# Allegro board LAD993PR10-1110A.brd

Outline 310.04 x 134.8 mm; copper layers: TOP, GND1, IN1, VCC, IN2, IN3, GND2, IN4, GND3, BOTTOM. Coordinates in mm from the lower left corner of the outline.

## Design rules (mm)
constraint set DEFAULT: min track width 0.114
net group CLK_S15(12)/20(15): nets CLK_PCIE_SSD CLK_PCIE_SSD#
net group DDI1_DDPB_CTRLDAT: nets DDI1_DDPB_CTRLCLK DDI1_DDPB_CTRLDAT
net group DIFFPAIR0: nets DMIC_CLK_CAM DMIC_DATA_CAM
net group DIFFPAIR1: nets CLK_SMB DAT_SMB
net group DIFFPAIR2: nets TMDS_L_TX2N TMDS_L_TX2P
net group DIFFPAIR3: nets TMDS_L_TX1N TMDS_L_TX1P
net group DIFFPAIR4: nets TMDS_L_TX0N TMDS_L_TX0P
net group DIFFPAIR5: nets TMDS_L_TXCN TMDS_L_TXCP
net group DP1: nets N123984002 N123984213
net group DP2: nets N123984081 N123985122
net group DP3: nets N57527 V3N
net group DP4: nets N122477585 V2N
net group DP5: nets N122476680 V1N
net group DP6: nets ISUMN_SA ISUMP_SA
net group DP12: nets GNDS_SENSE_VGA VDDS_SENSE_VGA
net group DP13: nets VCCSA_SENSE VSSSA_SENSE
net group DP_I2CB_SCL: nets I2CB_SCL SYS_PEX_RST_MON#
net group DP_N35924928: nets N35924928 N35928308
net group DP_STRAP: nets STRAP1 STRAP2
net group HDMI: nets TMDS_T_TX1N TMDS_T_TX1P
net group RTC: nets PCH_RTCX1 PCH_RTCX2
net group S-18(12)/18(12): nets XTAL_OUT XTALIN
net group SATA: nets SATA_PTX_DRX_N1B_RC SATA_PTX_DRX_P1B_RC
net group USB2.0: nets USBP2_R_D+ USBP2_R_D-
net group VSS_SENSE: nets VCCGT_SENSE VSSGT_SENSE
net group W-16: nets +FBA_VREFC0 +FBC_VREFC1
net group W-60: nets +EDPVDD +INV_PWR_SRC
net group 50H_W4.5(3.7)-T14B: nets CLK_PCI_LPC_MEC CLK_PCI_LPDEBUG CLKOUT_LPC0 CLKOUT_LPC1
net group 85H-CLK_4.3/3.6/3.6/4.3-T14B: nets CLK_PCIE_LAN CLK_PCIE_LAN# CLK_PCIE_WLAN CLK_PCIE_WLAN# CLK_PEG_N16P CLK_PEG_N16P# CPU_24MHZ_N CPU_24MHZ_P PCH_CPU_BCLK_N PCH_CPU_BCLK_P PCH_CPU_PCIBCLK_N PCH_CPU_PCIBCLK_P
net group 85H-PCIE_4.3/3.6/3.6/4.3-T14B: nets SATA_PRX_SSDTX_N0A SATA_PRX_SSDTX_P0A SATA_PTX_SSDRX_N0A SATA_PTX_SSDRX_N0A_C SATA_PTX_SSDRX_P0A SATA_PTX_SSDRX_P0A_C
net group DDRAC_S12/25: nets DDR_CKE0_DIMMA DDR_CKE1_DIMMA DDR_CS0_DIMMA# DDR_CS1_DIMMA# M_ODT0 M_ODT1
net group DDRAD0_S8/25: nets DDR_A_D0 DDR_A_D1 DDR_A_D2 DDR_A_D3 DDR_A_D4 DDR_A_D5 DDR_A_D6 DDR_A_D7
net group DDRAD1_S8/25: nets DDR_A_D8 DDR_A_D9 DDR_A_D10 DDR_A_D11 DDR_A_D12 DDR_A_D13 DDR_A_D14 DDR_A_D15
net group DDRAD2_S8/25: nets DDR_A_D16 DDR_A_D17 DDR_A_D18 DDR_A_D19 DDR_A_D20 DDR_A_D21 DDR_A_D22 DDR_A_D23
net group DDRAD3_S8/25: nets DDR_A_D24 DDR_A_D25 DDR_A_D26 DDR_A_D27 DDR_A_D28 DDR_A_D29 DDR_A_D30 DDR_A_D31
net group DDRAD4_S8/25: nets DDR_A_D32 DDR_A_D33 DDR_A_D34 DDR_A_D35 DDR_A_D36 DDR_A_D37 DDR_A_D38 DDR_A_D39
net group DDRAD5_S8/25: nets DDR_A_D40 DDR_A_D41 DDR_A_D42 DDR_A_D43 DDR_A_D44 DDR_A_D45 DDR_A_D46 DDR_A_D47
net group DDRAD6_S8/25: nets DDR_A_D48 DDR_A_D49 DDR_A_D50 DDR_A_D51 DDR_A_D52 DDR_A_D53 DDR_A_D54 DDR_A_D55
net group DDRAD7_S8/25: nets DDR_A_D56 DDR_A_D57 DDR_A_D58 DDR_A_D59 DDR_A_D60 DDR_A_D61 DDR_A_D62 DDR_A_D63
net group DDRAMA_S12/25: nets DDR_A_ACT# DDR_A_ALERT# DDR_A_BG0 DDR_A_BG1 DDR_A_BS0 DDR_A_BS1 DDR_A_CAS# DDR_A_MA0 DDR_A_MA1 DDR_A_MA2 DDR_A_MA3 DDR_A_MA4 DDR_A_MA5 DDR_A_MA6 DDR_A_MA7 DDR_A_MA8 DDR_A_MA9 DDR_A_MA10 DDR_A_MA11 DDR_A_MA12 DDR_A_MA13 DDR_A_PAR DDR_A_RAS# DDR_A_WE#
net group DDRBC_S12/25: nets DDR_CKE2_DIMMB DDR_CKE3_DIMMB DDR_CS2_DIMMB# DDR_CS3_DIMMB# M_ODT2 M_ODT3
net group DDRBD0_S8/25: nets DDR_B_D0 DDR_B_D1 DDR_B_D2 DDR_B_D3 DDR_B_D4 DDR_B_D5 DDR_B_D6 DDR_B_D7
net group DDRBD1_S8/25: nets DDR_B_D8 DDR_B_D9 DDR_B_D10 DDR_B_D11 DDR_B_D12 DDR_B_D13 DDR_B_D14 DDR_B_D15
net group DDRBD2_S8/25: nets DDR_B_D16 DDR_B_D17 DDR_B_D18 DDR_B_D19 DDR_B_D20 DDR_B_D21 DDR_B_D22 DDR_B_D23
net group DDRBD3_S8/25: nets DDR_B_D24 DDR_B_D25 DDR_B_D26 DDR_B_D27 DDR_B_D28 DDR_B_D29 DDR_B_D30 DDR_B_D31
net group DDRBD4_S8/25: nets DDR_B_D32 DDR_B_D33 DDR_B_D34 DDR_B_D35 DDR_B_D36 DDR_B_D37 DDR_B_D38 DDR_B_D39
net group DDRBD5_S8/25: nets DDR_B_D40 DDR_B_D41 DDR_B_D42 DDR_B_D43 DDR_B_D44 DDR_B_D45 DDR_B_D46 DDR_B_D47
net group DDRBD6_S8/25: nets DDR_B_D48 DDR_B_D49 DDR_B_D50 DDR_B_D51 DDR_B_D52 DDR_B_D53 DDR_B_D54 DDR_B_D55
net group DDRBD7_S8/25: nets DDR_B_D56 DDR_B_D57 DDR_B_D58 DDR_B_D59 DDR_B_D60 DDR_B_D61 DDR_B_D62 DDR_B_D63
net group DDRBMA_S12/25: nets DDR_B_ACT# DDR_B_ALERT# DDR_B_BG0 DDR_B_BG1 DDR_B_BS0 DDR_B_BS1 DDR_B_CAS# DDR_B_MA0 DDR_B_MA1 DDR_B_MA2 DDR_B_MA3 DDR_B_MA4 DDR_B_MA5 DDR_B_MA6 DDR_B_MA7 DDR_B_MA8 DDR_B_MA9 DDR_B_MA10 DDR_B_MA11 DDR_B_MA12 DDR_B_MA13 DDR_B_PAR DDR_B_RAS# DDR_B_WE#
net group DDRCLK_S16/25: nets M_CLK_DDR0 M_CLK_DDR1 M_CLK_DDR2 M_CLK_DDR3 M_CLK_DDR#0 M_CLK_DDR#1 M_CLK_DDR#2 M_CLK_DDR#3
net group DDRDQS_S25/25: nets DDR_A_DQS0 DDR_A_DQS1 DDR_A_DQS2 DDR_A_DQS3 DDR_A_DQS4 DDR_A_DQS5 DDR_A_DQS6 DDR_A_DQS7 DDR_A_DQS#0 DDR_A_DQS#1 DDR_A_DQS#2 DDR_A_DQS#3 DDR_A_DQS#4 DDR_A_DQS#5 DDR_A_DQS#6 DDR_A_DQS#7 DDR_B_DQS0 DDR_B_DQS1 DDR_B_DQS2 DDR_B_DQS3 DDR_B_DQS4 DDR_B_DQS5 DDR_B_DQS6 DDR_B_DQS7 DDR_B_DQS#0 DDR_B_DQS#1 DDR_B_DQS#2 DDR_B_DQS#3 DDR_B_DQS#4 DDR_B_DQS#5 DDR_B_DQS#6 DDR_B_DQS#7
net group DMI_S12/15: nets DMI_CRX_PTX_N0 DMI_CRX_PTX_N1 DMI_CRX_PTX_N2 DMI_CRX_PTX_N3 DMI_CRX_PTX_P0 DMI_CRX_PTX_P1 DMI_CRX_PTX_P2 DMI_CRX_PTX_P3 DMI_CTX_PRX_N0 DMI_CTX_PRX_N1 DMI_CTX_PRX_N2 DMI_CTX_PRX_N3 DMI_CTX_PRX_P0 DMI_CTX_PRX_P1 DMI_CTX_PRX_P2 DMI_CTX_PRX_P3
net group DP_FBC_ABI#_L: nets FBC_ABI#_L
net group EDP_S12/15: nets EDP_AUXN EDP_AUXN_C EDP_AUXN_R EDP_AUXP EDP_AUXP_C EDP_AUXP_R EDP_TXN0 EDP_TXN0_C EDP_TXN0_R EDP_TXN1 EDP_TXN1_C EDP_TXN1_R EDP_TXN2 EDP_TXN2_C EDP_TXN2_R EDP_TXN3 EDP_TXN3_C EDP_TXN3_R EDP_TXP0 EDP_TXP0_C EDP_TXP0_R EDP_TXP1 EDP_TXP1_C EDP_TXP1_R EDP_TXP2 EDP_TXP2_C EDP_TXP2_R EDP_TXP3 EDP_TXP3_C EDP_TXP3_R
net group FBCLK_S(20)12/(20)12: nets FBA_CLK0 FBA_CLK0# FBA_CLK1 FBA_CLK1# FBC_CLK0 FBC_CLK0# FBC_CLK1 FBC_CLK1#
net group FBCMD_S20(16)/20(16): nets FBC_ABI#_H FBC_CAS#_L FBC_MA0_MA10_L FBC_MA1_MA9_L FBC_MA2_BA0_L FBC_MA4_BA2_H FBC_MA6_MA11_H FBC_MA7_MA8_H FBC_MA12_RFU_L FBC_RST#_L FBC_WE#_H
net group FBWCK_S16/16: nets FBA_WCK0 FBA_WCK0_N FBA_WCK1 FBA_WCK1_N FBA_WCK2 FBA_WCK2_N FBA_WCK3 FBA_WCK3_N FBC_WCK0 FBC_WCK0_N FBC_WCK1 FBC_WCK1_N FBC_WCK2 FBC_WCK2_N FBC_WCK3 FBC_WCK3_N
net group HDMI_S16(12)/16(12): nets IFPC_CLK_CN IFPC_CLK_CP IFPC_CLK_N IFPC_CLK_P IFPC_TX0_CN IFPC_TX0_CP IFPC_TX0_N IFPC_TX0_P IFPC_TX1_CN IFPC_TX1_CP IFPC_TX1_N IFPC_TX1_P IFPC_TX2_CN IFPC_TX2_CP IFPC_TX2_N IFPC_TX2_P TMDS_T_TX0N TMDS_T_TX0P TMDS_T_TX2N TMDS_T_TX2P TMDS_T_TXCN TMDS_T_TXCP
net group LAN_S30/30: nets MDI0+ MDI0- MDI1+ MDI1- MDI2+ MDI2- MDI3+ MDI3- MDO0+ MDO0- MDO1+ MDO1- MDO2+ MDO2- MDO3+ MDO3-
net group PCIE_S12/15: nets PCIE_PRX_LANTX_N3_C PCIE_PRX_LANTX_N5 PCIE_PRX_LANTX_P3_C PCIE_PRX_LANTX_P5 PCIE_PRX_SSDTX_N10 PCIE_PRX_SSDTX_N11 PCIE_PRX_SSDTX_N12 PCIE_PRX_SSDTX_P10 PCIE_PRX_SSDTX_P11 PCIE_PRX_SSDTX_P12 PCIE_PRX_WLANTX_N6 PCIE_PRX_WLANTX_P6 PCIE_PTX_LANRX_N5 PCIE_PTX_LANRX_N5_C PCIE_PTX_LANRX_P5 PCIE_PTX_LANRX_P5_C PCIE_PTX_SSDRX_N10 PCIE_PTX_SSDRX_N10_C PCIE_PTX_SSDRX_N11 PCIE_PTX_SSDRX_N11_C PCIE_PTX_SSDRX_N12 PCIE_PTX_SSDRX_N12_C PCIE_PTX_SSDRX_P10 PCIE_PTX_SSDRX_P10_C PCIE_PTX_SSDRX_P11 PCIE_PTX_SSDRX_P11_C PCIE_PTX_SSDRX_P12 PCIE_PTX_SSDRX_P12_C PCIE_PTX_WLANRX_N6 PCIE_PTX_WLANRX_P6 PCIE_PTX_WLANRX_RE_N6 PCIE_PTX_WLANRX_RE_P6
net group PEG_S12/15: nets PEG_GTX_C_HRX_N0 PEG_GTX_C_HRX_N1 PEG_GTX_C_HRX_N2 PEG_GTX_C_HRX_N3 PEG_GTX_C_HRX_N4 PEG_GTX_C_HRX_N5 PEG_GTX_C_HRX_N6 PEG_GTX_C_HRX_N7 PEG_GTX_C_HRX_N8 PEG_GTX_C_HRX_N9 PEG_GTX_C_HRX_N10 PEG_GTX_C_HRX_N11 PEG_GTX_C_HRX_N12 PEG_GTX_C_HRX_N13 PEG_GTX_C_HRX_N14 PEG_GTX_C_HRX_N15 PEG_GTX_C_HRX_P0 PEG_GTX_C_HRX_P1 PEG_GTX_C_HRX_P2 PEG_GTX_C_HRX_P3 PEG_GTX_C_HRX_P4 PEG_GTX_C_HRX_P5 PEG_GTX_C_HRX_P6 PEG_GTX_C_HRX_P7 PEG_GTX_C_HRX_P8 PEG_GTX_C_HRX_P9 PEG_GTX_C_HRX_P10 PEG_GTX_C_HRX_P11 PEG_GTX_C_HRX_P12 PEG_GTX_C_HRX_P13 PEG_GTX_C_HRX_P14 PEG_GTX_C_HRX_P15 PEG_GTX_HRX_N0 PEG_GTX_HRX_N1 PEG_GTX_HRX_N2 PEG_GTX_HRX_N3 PEG_GTX_HRX_N4 PEG_GTX_HRX_N5 PEG_GTX_HRX_N6 PEG_GTX_HRX_N7 PEG_GTX_HRX_N8 PEG_GTX_HRX_N9 PEG_GTX_HRX_N10 PEG_GTX_HRX_N11 PEG_GTX_HRX_N12 PEG_GTX_HRX_N13 PEG_GTX_HRX_N14 PEG_GTX_HRX_N15 PEG_GTX_HRX_P0 PEG_GTX_HRX_P1 PEG_GTX_HRX_P2 PEG_GTX_HRX_P3 PEG_GTX_HRX_P4 PEG_GTX_HRX_P5 PEG_GTX_HRX_P6 PEG_GTX_HRX_P7 PEG_GTX_HRX_P8 PEG_GTX_HRX_P9 PEG_GTX_HRX_P10 PEG_GTX_HRX_P11 PEG_GTX_HRX_P12 PEG_GTX_HRX_P13 PEG_GTX_HRX_P14 PEG_GTX_HRX_P15 PEG_HTX_C_GRX_N0 PEG_HTX_C_GRX_N1 PEG_HTX_C_GRX_N2 PEG_HTX_C_GRX_N3 PEG_HTX_C_GRX_N4 PEG_HTX_C_GRX_N5 PEG_HTX_C_GRX_N6 PEG_HTX_C_GRX_N7 PEG_HTX_C_GRX_N8 PEG_HTX_C_GRX_N9 PEG_HTX_C_GRX_N10 PEG_HTX_C_GRX_N11 PEG_HTX_C_GRX_N12 PEG_HTX_C_GRX_N13 PEG_HTX_C_GRX_N14 PEG_HTX_C_GRX_N15 PEG_HTX_C_GRX_P0 PEG_HTX_C_GRX_P1 PEG_HTX_C_GRX_P2 PEG_HTX_C_GRX_P3 PEG_HTX_C_GRX_P4 PEG_HTX_C_GRX_P5 PEG_HTX_C_GRX_P6 PEG_HTX_C_GRX_P7 PEG_HTX_C_GRX_P8 PEG_HTX_C_GRX_P9 PEG_HTX_C_GRX_P10 PEG_HTX_C_GRX_P11 PEG_HTX_C_GRX_P12 PEG_HTX_C_GRX_P13 PEG_HTX_C_GRX_P14 PEG_HTX_C_GRX_P15 PEG_HTX_GRX_N0 PEG_HTX_GRX_N1 PEG_HTX_GRX_N2 PEG_HTX_GRX_N3 PEG_HTX_GRX_N4 PEG_HTX_GRX_N5 PEG_HTX_GRX_N6 PEG_HTX_GRX_N7 PEG_HTX_GRX_N8 PEG_HTX_GRX_N9 PEG_HTX_GRX_N10 PEG_HTX_GRX_N11 PEG_HTX_GRX_N12 PEG_HTX_GRX_N13 PEG_HTX_GRX_N14 PEG_HTX_GRX_N15 PEG_HTX_GRX_P0 PEG_HTX_GRX_P1 PEG_HTX_GRX_P2 PEG_HTX_GRX_P3 PEG_HTX_GRX_P4 PEG_HTX_GRX_P5 PEG_HTX_GRX_P6 PEG_HTX_GRX_P7 PEG_HTX_GRX_P8 PEG_HTX_GRX_P9 PEG_HTX_GRX_P10 PEG_HTX_GRX_P11 PEG_HTX_GRX_P12 PEG_HTX_GRX_P13 PEG_HTX_GRX_P14 PEG_HTX_GRX_P15
net group POWER-20: nets 1.2V_DDR_OT 1V8_GFX_RUN 1VS_GFX_PG 3VS 3VS_TP 5VS +0.6VS +0.6VSP +0.95VSP +1.0VSP +1.2V_DDR +1.2V_DDRP +1.2V_PWROK +1.2V_VCCPLL_OC +1.8V_AVDD +1.8V_DVDD +1.8V_GFX_RUN +1.8V_PLLVDD +1.8VS +1.8VSP +1.35VS_VGA +1.35VS_VGAP +1.35VS_VGAP_B+ +1V_MPHY +1V_MPHY_MPHYPLL +1V_PCH +1V_PCH_AZPLL +1V_PCH_CLK5 +1V_PCH_PRIM +1V_PCH_USBPLL +1V_VCCDSW +1VALWP +1VS_GFX +3.3VDX_SSD +3V_DVDD +3V_PCH_AZIO +3V_PCH_DSW +3V_PCH_SPI +3V_ROM +3VALWP +3VLP +3VS_CAM +3VS_TP +3VS_WLAN +5V_AVDD +5V_CHGUSB_1 +5V_CHGUSB_2 +5V_PVDD +5VALWP +5VS +5VS_HDD +5VS_KBL +5VS_TS +19VB_1VALWP +19VB_+0.95VSP +19VB_+1.0VSP +19VB_+1.8VSP +CHGRTC +DC_IN +DCPRTC +GPCPLL_AVDD +GPU_CORE_VDDS +IFP_PLLVDD +LAN_VDD +NVVDDS_B+ +PEX_PLL_HVDD +SP_PLLVDD +V_DAC +VCCIO +VCCIO_PG +VCCST +VCCSTG +VDISPLAY_VCC +VGA_B+ -DC_IN B++ B+_CAM BATT++ BST_3V BST_5V CHG_B+ DH1_NVVDD DH1_NVVDDS DH2_NVVDD DL1_NVVDD DL1_NVVDDS DL2_NVVDD EC_AGND FB_3V FB_5V GVDD LDO_1VALWP LDO_+0.95VSP LDO_+1.0VSP LDO_+1.8VSP LG_3V LG_5V LX1_NVVDD LX1_NVVDDS LX2_NVVDD LX_1VALWP LX_3V LX_5V LX_+0.95VSP LX_+1.0VSP LX_+1.8VSP LX_CHG N120976432 N121795600 N122017994 N123983992 N123984041 N123984461 N128731318 N128835022 N128884118 N128885130 N129089927 N129090627 N131680753 N131681151 N131748830 PQ703_S SNUB_+0.95VSP SNUB_+1.0VSP SNUB_+1.8VSP SW_+1.35VS_VGAP UG_3V UG_5V VBATT VCCGT_B+ VCCST VCCSTG VCORE_B+ VIN
net group S-5(4)/5(4): nets DDC_CLK_HDMI DDC_DAT_HDMI IFPC_I2C_CLK IFPC_I2C_DAT
net group S_10/10: nets CODEC_SDOUT_R N131741387 REMOTE1+ REMOTE1- REMOTE2+ REMOTE2- VCCSENSE_VGA VR_SVID_ALERT# VR_SVID_ALERT#_C VR_SVID_ALERT#_R VR_SVID_CLK VR_SVID_CLK_C VR_SVID_DATA VR_SVID_DATA_C VSSSENSE_VGA
net group S_12/12: nets EC_SPI_CS# EC_SPI_CS#_R EC_SPI_SI EC_SPI_SI_R EC_SPI_SO EC_SPI_SO_R PCH_SPI_CS# PCH_SPI_HOLD# PCH_SPI_HOLD#_R PCH_SPI_SI PCH_SPI_SI_R PCH_SPI_SO PCH_SPI_SO_R PCH_SPI_WP# PCH_SPI_WP#_R PCIE_RCOMPN PCIE_RCOMPP
net group S_15/15: nets CODEC_BITCLK_R H_DRAMRST# LPC_LAD0 LPC_LAD1 LPC_LAD2 LPC_LAD3 LPC_LFRAME# MEC_XTAL1 MEC_XTAL1_R MEC_XTAL2 PCH_DPWROK PCH_PLTRST# PCH_PWROK PCH_RSMRST# PCH_RSMRST#_R PCH_RTCRST# PCH_SRTCRST# PEG_RCOMP SYS_PWROK SYS_RESET# XTAL24_IN XTAL24_OUT XTALOUT XTALSSIN XTLI XTLO
net group S_20/20: nets EC_SPI_CLK EC_SPI_CLK_R H_CPUPWRGD H_VCCST_PWRGD HDA_BITCLK HDA_BITCLK_AUDIO PCH_SPI_CLK PCH_SPI_CLK_R PECI_EC PECI_EC_R PLTRST_CPU# VCCST_PWRGD_CPU
net group S_25/25: nets EDP_COMP
net group SATA_PRX_DTX_P1B_RC: nets SATA_PRX_DTX_N1B_RC
net group SATA_S12/15: nets SATA_PRX_DTX_N1B SATA_PRX_DTX_P1B SATA_PRX_DTX_P1B_RC SATA_PTX_DRX_N1B SATA_PTX_DRX_P1B
net group SM: nets PCH_SMBCLK SMBCLK SML0_SMBCLK SML1_SMBCLK SUSCLK SUSCLK_R
net group USB2.0_S12/15: nets USB20_N1 USB20_N2 USB20_N3 USB20_N4 USB20_N4_R USB20_N7 USB20_N9 USB20_N9_R USB20_N12 USB20_N12_R USB20_P1 USB20_P2 USB20_P3 USB20_P4 USB20_P4_R USB20_P7 USB20_P9 USB20_P9_R USB20_P12 USB20_P12_R USBP1_R_D+ USBP1_R_D- USBP2_D+ USBP2_D-
net group USB3.0_S12/15: nets USB3RN1 USB3RN1_D- USB3RN2 USB3RN2_D- USB3RN3 USB3RP1 USB3RP1_D+ USB3RP2 USB3RP2_D+ USB3RP3 USB3T_N1 USB3T_N2 USB3T_P1 USB3T_P2 USB3TN1 USB3TN1_D- USB3TN2 USB3TN2_D- USB3TN3 USB3TP1 USB3TP1_D+ USB3TP2 USB3TP2_D+ USB3TP3
net group W-10: nets FBVDDQ_SENSE VCC_SENSE VCCIO_SENSE VSS_SENSE VSSIO_SENSE
net group W-20: nets +RTCBATT +RTCVCC +RTCVCC_VBAT +V_DDR_REFA +V_DDR_REFA_R +V_DDR_REFB +V_DDR_REFB_R
net group W-40: nets +LAN_IO AUD_PORTA_L_R_B AUD_PORTA_R_R_B AUD_SPK_L+ AUD_SPK_L+_C AUD_SPK_L- AUD_SPK_L-_C AUD_SPK_R+ AUD_SPK_R+_C AUD_SPK_R- AUD_SPK_R-_C RING2 RING2_R SLEEVE SLEEVE_R
net group W-50OHM: nets CLKREQ_PCIE#0 CLKRUN# H_CATERR# H_PROCHOT# H_PROCHOT#_R H_PROCHOT_EC H_THERMTRIP# H_THERMTRIP#_R HDA_CODEC_SDIN0 HDA_SDIN0 HDA_SDIN0_AUDIO HDA_SDOUT HDA_SDOUT_AUDIO HDA_SYNC HDA_SYNC_AUDIO LAN_CLKREQ# PECI SRCCLKREQ1# SRCCLKREQ4# SRCCLKREQ5# SRCCLKREQ7# SRCCLKREQ8# SRCCLKREQ9# SRCCLKREQ10# SRCCLKREQ11# SRCCLKREQ13# SRCCLKREQ14# SRCCLKREQ15# SSD_CLK_REQ# USB2_COMP VGA_CLK_REQ# WLAN_CLK_REQ#
nets with their own width: min track width 0.254; nets N18094850 N19473597
nets with their own width: min track width 0.381; nets N19473413
nets with their own width: min track width 0.508; nets 5VS_FAN2 +2.5V_MEM +2.5VSP_ON GND N128884110 N131311358
nets with their own width: min track width 0.635; nets +5VALW

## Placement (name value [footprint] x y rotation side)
CA1  4.7U_0603_6.3V6K  [C_0603]  288.17 27.49 0 top
CA2  0.1U_0402_10V6K  [C_0402]  288.41 28.57 0 top
CA3  0.1U_0402_10V6K  [C_0402]  285.63 28.57 0 top
CA4  1U_0402_6.3V6K  [C_0402]  290.2 39.03 90 top
CA7  1U_0402_6.3V6K  [C_0402]  289.77 33.07 180 top
CA8  4.7U_0603_6.3V6K  [C_0603]  275.66 20.82 180 top
CA9  0.1U_0402_10V6K  [C_0402]  275.42 21.96 180 top
CA10  0.68U_0603_16V6K  [C_0603]  285.19 37.96 0 top
CA11  10U_0603_6.3V6M~D  [C_0603]  278.33 30.98 90 top
CA12  0.1U_0402_10V6K  [C_0402]  279.41 30.9 90 top
CA13  10U_0603_6.3V6M~D  [C_0603]  280.49 30.98 90 top
CA14  0.1U_0402_10V6K  [C_0402]  281.57 30.9 90 top
CA15  1U_0402_6.3V6K  [C_0402]  286.55 27.68 180 top
CA16  2.2U_0402_6.3V6M  [C_0402]  287.74 23.51 180 top
CA17  0.1U_0402_10V6K  [C_0402]  284.62 20.13 270 top
CA18  4.7U_0603_6.3V6K  [C_0603]  287.66 18.98 90 top
CA19  4.7U_0603_6.3V6K  [C_0603]  287.98 22.47 180 top
CA20  1U_0402_6.3V6K  [C_0402]  285.63 28.45 270 bottom
CA21  1U_0402_6.3V6K  [C_0402]  283.73 20.13 270 top
CA22  10U_0603_6.3V6M  [C_0603]  284.49 29.64 180 bottom
CA23  10U_0603_6.3V6M  [C_0603]  281.63 21.58 180 bottom
CA24  0.1U_0402_10V6K  [C_0402]  278.47 20.06 180 top
CA25  4.7U_0603_6.3V6K  [C_0603]  275.66 19.55 180 top
CA26  0.1U_0402_10V6K  [C_0402]  275.42 27.55 180 top
CA27  4.7U_0603_6.3V6K  [C_0603]  275.92 24.88 180 top
CA28  0.1U_0402_10V6K  [C_0402]  275.42 22.85 180 top
CA29  0.1U_0402_10V6K  [C_0402]  279.83 17.45 90 top
CA30  22P_0402_50V8J  [C_0402]  272.22 25.45 0 top
CA31  .1U_0402_16V7K  [C_0402]  273.64 25.9 180 bottom
CA32  .1U_0402_16V7K  [C_0402]  275.41 23.92 90 bottom
CA33  33P_0402_50V8J  [C_0402]  272.68 24.04 90 bottom
CA34  0.01U_0201_16V7  [C_0201]  270.46 22.56 90 top
CA35  0.01U_0201_16V7  [C_0201]  273.25 22.68 90 top
CA36  1000P_0402_50V7K  [C_0402]  278.06 15.66 180 top
CA37  1000P_0402_50V7K  [C_0402]  275.37 15.66 0 top
CA38  1000P_0402_50V7K  [C_0402]  273.24 15.66 180 top
CA39  1000P_0402_50V7K  [C_0402]  270.55 15.66 0 top
CA40  100P_0402_50V8J  [C_0402]  292.57 18.91 180 top
CA41  100P_0402_50V8J  [C_0402]  296.48 16.88 0 top
CA42  100P_0402_50V8J  [C_0402]  296.99 12.06 0 bottom
CA43  100P_0402_50V8J  [C_0402]  293.25 18.23 270 bottom
CA44  680P_0402_50V7K  [C_0402]  259.39 10.71 180 bottom
CA45  680P_0402_50V7K  [C_0402]  261.81 10.71 0 bottom
CA46  330P_0402_50V7K  [C_0402]  257.92 14.67 0 bottom
CA47  330P_0402_50V7K  [C_0402]  268.26 15.2 0 bottom
CA48  0.22U_0603_50V7K  [C_0603]  258.99 16.98 270 bottom
CA49  0.22U_0603_50V7K  [C_0603]  261.25 14.62 0 bottom
CA50  0.22U_0603_50V7K  [C_0603]  264.42 14.62 0 bottom
CA51  0.22U_0603_50V7K  [C_0603]  268.08 16.14 90 bottom
CA52  1000P_0402_50V7K  [C_0402]  258.79 18.79 180 bottom
CA53  10U_0603_25V6M  [C_0603]  258.85 19.83 180 bottom
CA54  1000P_0402_50V7K  [C_0402]  268.27 20.58 0 top
CA55  0.1U_0402_25V6  [C_0402]  271.79 18.84 90 top
CA56  10U_0603_25V6M  [C_0603]  270.65 18.85 90 top
CA57  0.1U_0402_25V6  [C_0402]  258.79 17.9 180 bottom
CA60  680P_0402_50V7K  [C_0402]  296.98 9.36 225 bottom
CA61  680P_0402_50V7K  [C_0402]  294.14 18.23 270 bottom
CA62  10P_0402_25V8J  [C_0402]  275.42 26.66 180 top
CA63  10U_0603_6.3V6M  [C_0603]  284.49 29.64 180 top
CA64  10U_0603_6.3V6M~D  [C_0603]  295.41 15.55 270 top
CA65  10U_0603_6.3V6M~D  [C_0603]  294.14 15.55 270 top
CA66  1U_0603_25V6  [C_0603]  258.9 27.04 0 bottom
CA67  0.1U_0402_25V6  [C_0402]  262.9 30.65 90 bottom
CC4  12P_0402_50V8J  [C_0402]  169.47 16.47 0 top
CC5  12P_0402_50V8J  [C_0402]  184.28 24.28 0 top
CC27  1U_0402_6.3V6K  [C_0402]  154.52 18.82 270 bottom
CC298  0.1U_0402_16V7K  [C_0402]  131.66 75.43 180 top
CD1  1U_0402_6.3V6K  [C_0402]  96.61 42.79 180 top
CD2  1U_0402_6.3V6K  [C_0402]  79.85 43.03 0 top
CD3  1U_0402_6.3V6K  [C_0402]  138.65 41.12 0 top
CD4  1U_0402_6.3V6K  [C_0402]  138.65 40.24 0 top
CD5  10U_0603_6.3V6M  [C_0603]  112.62 44.43 0 top
CD6  10U_0603_6.3V6M  [C_0603]  102.05 44.44 0 top
CD7  10U_0603_6.3V6M  [C_0603]  131.9 43.81 180 top
CD8  10U_0603_6.3V6M  [C_0603]  89.76 44.05 180 top
CD9  10U_0603_6.3V6M  [C_0603]  138.64 39.09 180 top
CD10  10U_0603_6.3V6M  [C_0603]  137.23 41.6 270 top
CD11  330U_X_2VM_R6M  [C_X]  91.53 15.48 180 bottom
CD12  1U_0402_6.3V6K  [C_0402]  138.11 31.23 0 top
CD13  10U_0603_6.3V6M  [C_0603]  136.6 29.96 180 top
CD14  10U_0603_6.3V6M  [C_0603]  136.6 31.23 180 top
CD15  10U_0603_6.3V6M  [C_0603]  138.12 29.96 0 top
CD16  0.1U_0402_10V6K  [C_0402]  135.8 43.08 90 top
CD17  2.2U_0402_6.3V6M  [C_0402]  134.91 43.08 90 top
CD19  1U_0402_6.3V6K  [C_0402]  94.42 19.55 0 top
CD20  1U_0402_6.3V6K  [C_0402]  83.88 19.68 0 top
CD21  1U_0402_6.3V6K  [C_0402]  102.71 19.52 0 top
CD22  1U_0402_6.3V6K  [C_0402]  109.46 19.52 180 top
CD23  10U_0603_6.3V6M  [C_0603]  121.39 28.41 180 top
CD24  10U_0603_6.3V6M  [C_0603]  132.69 28.54 180 top
CD25  10U_0603_6.3V6M  [C_0603]  116.82 19.78 0 top
CD26  10U_0603_6.3V6M  [C_0603]  104.34 28.57 0 top
CD27  10U_0603_6.3V6M  [C_0603]  141.61 26.47 270 top
CD28  10U_0603_6.3V6M  [C_0603]  140.34 26.47 270 top
CD29  0.1U_0402_10V6K  [C_0402]  113.32 19.58 90 top
CD30  1U_0402_6.3V6K  [C_0402]  138.86 27.69 90 top
CD31  1U_0402_6.3V6K  [C_0402]  139.75 27.69 90 top
CD32  1U_0402_6.3V6K  [C_0402]  136.32 22.13 180 top
CD33  330U_2.5V_M  [C_APXK2R5ARA331MF451]  145.93 31.74 180 bottom
CD34  0.1U_0402_10V6K  [C_0402]  136.28 27.6 90 top
CD35  2.2U_0402_6.3V6M  [C_0402]  135.39 27.6 90 top
CD36  4.7U_0603_6.3V6K  [C_0603]  218.32 35.04 0 bottom
CD37  0.22U_0402_10V6K  [C_0402]  205.11 35.91 270 bottom
CD38  0.1U_0402_10V6K  [C_0402]  217.43 19.55 0 bottom
CD39  0.01U_0402_16V7K  [C_0402]  218.47 31.99 0 bottom
CD40  47P_0402_50V8J  [C_0402]  217.43 18.66 0 bottom
CD41  15P_0402_50V8J  [C_0402]  218.47 33.01 0 bottom
CD42  0.22U_0402_10V6K  [C_0402]  204.23 35.91 270 bottom
CD43  0.22U_0402_10V6K  [C_0402]  203.21 35.91 270 bottom
CD44  0.22U_0402_10V6K  [C_0402]  202.32 35.91 270 bottom
CD45  0.22U_0402_10V6K  [C_0402]  201.3 35.91 270 bottom
CD46  0.22U_0402_10V6K  [C_0402]  200.42 35.91 270 bottom
CD51  0.22U_0402_10V6K  [C_0402]  198.51 35.91 270 bottom
CD53  0.22U_0402_10V6K  [C_0402]  199.4 35.91 270 bottom
CD69  .1U_0402_16V7K  [C_0402]  96 16.63 90 bottom
CD70  10U_0603_6.3V6M  [C_0603]  123.17 43.28 0 top
CD71  10U_0603_6.3V6M  [C_0603]  116.94 32.49 0 top
CD72  10U_0603_6.3V6M  [C_0603]  100.34 31.68 90 top
CD73  10U_0603_6.3V6M  [C_0603]  96.75 43.92 180 top
CD74  1U_0402_6.3V6K  [C_0402]  84.06 32.36 180 top
CD75  1U_0402_6.3V6K  [C_0402]  94.7 32.5 180 top
CD76  1U_0402_6.3V6K  [C_0402]  127.62 32.23 180 top
CD77  1U_0402_6.3V6K  [C_0402]  102.04 43.3 0 top
CD78  1U_0402_6.3V6K  [C_0402]  106.34 32.41 90 top
CD79  1U_0402_6.3V6K  [C_0402]  112.61 43.28 0 top
CD80  1U_0402_6.3V6K  [C_0402]  98.39 19.52 0 top
CD81  1U_0402_6.3V6K  [C_0402]  127.34 19.52 0 top
CD82  1U_0402_6.3V6K  [C_0402]  104.61 19.52 0 top
CD83  1U_0402_6.3V6K  [C_0402]  100.42 19.52 0 top
CD84  10U_0603_6.3V6M  [C_0603]  113.13 28.54 0 top
CD85  10U_0603_6.3V6M  [C_0603]  98.15 28.41 180 top
CD86  10U_0603_6.3V6M  [C_0603]  87.83 30.47 180 top
CD87  10U_0603_6.3V6M  [C_0603]  73.35 19.8 180 top
CD88  10U_0603_6.3V6M  [C_0603]  137.84 21.55 0 top
CD89  10U_0603_6.3V6M  [C_0603]  137.84 20.28 0 top
CD90  10U_0603_6.3V6M  [C_0603]  136.81 20.28 180 top
CD91  1U_0402_6.3V6K  [C_0402]  258.76 21.78 180 bottom
CD92  1U_0402_6.3V6K  [C_0402]  258.84 22.72 90 bottom
CD93  1U_0402_6.3V6K  [C_0402]  260.94 22.98 180 bottom
CD94  1U_0402_6.3V6K  [C_0402]  263.66 23.03 90 bottom
CD95  1U_0402_6.3V6K  [C_0402]  264.55 23.03 90 bottom
CD96  0.1U_0402_10V6K  [C_0402]  113.92 32.13 90 top
CE1  0.1U_0402_10V7K~D  [C_0402]  213.24 34.33 90 top
CE2  0.1U_0402_10V6K  [C_0402]  134.82 16.11 0 top
CE4  1U_0402_6.3V6K  [C_0402]  121.67 15.76 90 top
CE5  1U_0402_6.3V6K  [C_0402]  126.32 15.84 180 top
CE6  10U_0603_6.3V6M~D  [C_0603]  122.62 15.97 0 top
CE8  0.047U_0402_16V4Z  [C_0402]  240.85 27.7 0 top
CE9  22P_0402_50V8J  [C_0402]  147.15 14.37 180 bottom
CE10  22P_0402_50V8J  [C_0402]  147.15 15.33 180 bottom
CE12  1U_0402_6.3V6K  [C_0402]  221.93 29.89 0 bottom
CE62  0.1U_0402_10V6K  [C_0402]  236.31 24.88 180 bottom
CE63  1000P_0402_50V7K  [C_0402]  231.78 35.37 270 top
CE64  1000P_0402_50V7K  [C_0402]  239.74 18.02 180 top
CE65  0.1U_0402_10V6K  [C_0402]  217.26 22.6 180 top
CE66  0.1U_0402_10V6K  [C_0402]  226.96 29.66 270 bottom
CE67  0.1U_0402_10V6K  [C_0402]  224.14 15.1 0 bottom
CE68  0.1U_0402_10V6K  [C_0402]  236.18 18.28 180 bottom
CE69  0.1U_0402_10V6K  [C_0402]  220.99 29 90 bottom
CE71  0.1U_0402_10V6K  [C_0402]  227.25 15.56 0 bottom
CE72  0.047U_0402_10V7K~D  [C_0402]  227.25 16.53 0 bottom
CE73  0.1U_0402_10V6K  [C_0402]  224.29 34.46 90 bottom
CE74  0.1U_0402_10V6K  [C_0402]  217.26 21.71 180 top
CE76  100P_0402_50V8J  [C_0402]  235.98 34.46 90 top
CE77  0.1U_0402_10V6K  [C_0402]  236.05 29.58 180 bottom
CE78  4.7P_0402_50V8C  [C_0402]  228.1 13.02 270 top
CE79  0.1U_0402_10V6K  [C_0402]  220.86 23.03 90 bottom
CE80  22P_0402_50V8J  [C_0402]  150.73 15.08 270 bottom
CE81  0.1U_0402_10V6K  [C_0402]  228.86 26.58 90 bottom
CE82  1000P_0402_50V7K  [C_0402]  232.99 21.48 180 bottom
CE84  100P_0402_50V8J  [C_0402]  221.62 32.07 270 bottom
CE85  0.1U_0402_10V6K  [C_0402]  236.31 27.55 180 bottom
CE86  47P_0402_50V8J  [C_0402]  236.31 25.77 180 bottom
CE87  2200P_0402_25V7K  [C_0402]  231.66 27.5 270 bottom
CE89  10U_0603_6.3V6M  [C_0603]  238.71 19.17 0 top
CE91  0.1U_0402_10V6K  [C_0402]  223.58 23.03 180 bottom
CE98  0.1U_0402_10V6K  [C_0402]  228.8 29.66 270 bottom
CE99  0.01U_0402_16V7K  [C_0402]  52.97 31.03 90 top
CE100  0.01U_0402_16V7K  [C_0402]  242.28 38.09 180 top
CE101  10P_0402_25V8J  [C_0402]  221.7 35.42 180 top
CE102  10P_0402_25V8J  [C_0402]  222.69 35.42 0 top
CE103  1U_0603_25V6  [C_0603]  213.38 22.8 90 top
CE104  0.1U_0402_10V6K  [C_0402]  227.34 32.12 0 bottom
CH5  0.22U_0201_6.3V6M  [C_0201]  134.63 92.75 0 bottom
CH6  0.22U_0201_6.3V6M  [C_0201]  134.63 93.39 0 bottom
CH7  0.22U_0201_6.3V6M  [C_0201]  136.15 91.73 0 bottom
CH8  0.22U_0201_6.3V6M  [C_0201]  136.15 92.37 0 bottom
CH9  0.22U_0201_6.3V6M  [C_0201]  134.63 90.72 0 bottom
CH10  0.22U_0201_6.3V6M  [C_0201]  134.63 91.35 0 bottom
CH11  0.22U_0201_6.3V6M  [C_0201]  136.15 90.34 0 bottom
CH12  0.22U_0201_6.3V6M  [C_0201]  136.15 89.7 0 bottom
CH13  0.22U_0201_6.3V6M  [C_0201]  134.63 88.69 0 bottom
CH14  0.22U_0201_6.3V6M  [C_0201]  134.63 89.32 0 bottom
CH15  0.22U_0201_6.3V6M  [C_0201]  136.15 88.31 0 bottom
CH16  0.22U_0201_6.3V6M  [C_0201]  136.15 87.67 0 bottom
CH17  0.22U_0201_6.3V6M  [C_0201]  134.63 86.65 0 bottom
CH18  0.22U_0201_6.3V6M  [C_0201]  134.63 87.29 0 bottom
CH19  0.22U_0201_6.3V6M  [C_0201]  136.15 85.64 0 bottom
CH20  0.22U_0201_6.3V6M  [C_0201]  136.15 86.27 0 bottom
CH21  0.22U_0201_6.3V6M  [C_0201]  134.63 85.26 0 bottom
CH22  0.22U_0201_6.3V6M  [C_0201]  134.63 84.62 0 bottom
CH23  0.22U_0201_6.3V6M  [C_0201]  136.15 83.61 0 bottom
CH24  0.22U_0201_6.3V6M  [C_0201]  136.15 84.24 0 bottom
CH25  0.22U_0201_6.3V6M  [C_0201]  134.63 83.23 0 bottom
CH26  0.22U_0201_6.3V6M  [C_0201]  134.63 82.59 0 bottom
CH27  0.22U_0201_6.3V6M  [C_0201]  136.15 81.57 0 bottom
CH28  0.22U_0201_6.3V6M  [C_0201]  136.15 82.21 0 bottom
CH29  0.22U_0201_6.3V6M  [C_0201]  134.63 81.19 0 bottom
CH30  0.22U_0201_6.3V6M  [C_0201]  134.63 80.56 0 bottom
CH31  0.22U_0201_6.3V6M  [C_0201]  136.15 79.54 0 bottom
CH32  0.22U_0201_6.3V6M  [C_0201]  136.15 80.18 0 bottom
CH33  0.22U_0201_6.3V6M  [C_0201]  134.63 79.16 0 bottom
CH34  0.22U_0201_6.3V6M  [C_0201]  134.63 78.53 0 bottom
CH35  0.22U_0201_6.3V6M  [C_0201]  136.15 77.51 0 bottom
CH36  0.22U_0201_6.3V6M  [C_0201]  136.15 78.15 0 bottom
CH45  8.2P_0402_50V8D  [C_0402]  175.48 18.07 0 bottom
CH46  8.2P_0402_50V8D  [C_0402]  174.62 18.07 180 bottom
CH47  15P_0402_50V8J  [C_0402]  182.89 45 90 bottom
CH48  18P_0402_50V8J  [C_0402]  182.89 44.14 270 bottom
CH50  10P_0402_25V8J  [C_0402]  179.38 18.79 0 bottom
CH51  10P_0402_25V8J  [C_0402]  175.29 25.43 0 top
CH52  1U_0402_6.3V6K  [C_0402]  174.63 22.93 270 top
CH53  1U_0402_6.3V6K  [C_0402]  174.51 19.75 270 top
CH70  0.1U_0402_10V6K  [C_0402]  165.74 23.05 270 top
CH80  1U_0402_6.3V6K  [C_0402]  168.6 25.76 90 top
CH82  1U_0402_6.3V6K  [C_0402]  171.33 34.92 90 top
CH100  0.022U_0402_16V7K  [C_0402]  110.37 20.51 270 top
CH101  0.022U_0402_16V7K  [C_0402]  68.16 44.8 0 top
CH102  10U_0603_6.3V6M  [C_0603]  123.23 85.02 90 top
CH103  10U_0603_6.3V6M  [C_0603]  123.2 87.68 90 top
CH104  10U_0603_6.3V6M  [C_0603]  123.19 91.57 270 top
CH106  1U_0402_6.3V6K  [C_0402]  125.04 96.44 0 top
CH110  1U_0402_6.3V6K  [C_0402]  123.2 93.59 270 top
CH111  10U_0603_6.3V6M  [C_0603]  120.25 96.14 270 top
CH112  10U_0603_6.3V6M  [C_0603]  121.74 85.23 180 top
CH113  10U_0603_6.3V6M  [C_0603]  123.64 97.65 0 top
CH114  10U_0603_6.3V6M  [C_0603]  121.79 86.58 180 top
CH115  10U_0603_6.3V6M  [C_0603]  120.48 98.99 90 top
CH116  10U_0603_6.3V6M  [C_0603]  123.64 98.87 0 top
CH117  10U_0603_6.3V6M  [C_0603]  124.15 100.09 0 top
CH118  10U_0603_6.3V6M  [C_0603]  101.24 80.62 90 top
CH119  10U_0603_6.3V6M  [C_0603]  106.02 80.43 90 top
CH120  10U_0603_6.3V6M  [C_0603]  102.88 76.63 270 top
CH121  10U_0603_6.3V6M  [C_0603]  99.25 78.51 0 top
CH122  10U_0603_6.3V6M  [C_0603]  107.72 79.99 90 top
CH123  10U_0603_6.3V6M  [C_0603]  113.87 76.57 180 top
CH124  10U_0603_6.3V6M  [C_0603]  99.59 80.62 90 top
CH125  10U_0603_6.3V6M  [C_0603]  111.35 79.32 90 top
CH126  10U_0603_6.3V6M  [C_0603]  117.99 76.63 270 top
CH127  10U_0603_6.3V6M  [C_0603]  121.74 81.4 180 top
CH128  10U_0603_6.3V6M  [C_0603]  123.18 76.4 0 top
CH129  22U_0603_6.3V6M  [C_0603]  124.66 60.7 0 top
CH130  22U_0603_6.3V6M  [C_0603]  124.66 59.3 0 top
CH131  22U_0603_6.3V6M  [C_0603]  124.66 57.9 0 top
CH132  22U_0603_6.3V6M  [C_0603]  124.66 56.51 0 top
CH133  1U_0402_6.3V6K  [C_0402]  122.68 100.04 90 top
CH134  1U_0402_6.3V6K  [C_0402]  121.12 101.32 180 top
CH135  1U_0402_6.3V6K  [C_0402]  120.69 98.08 180 top
CH136  47U_0603_6.3V6M  [C_0603]  121.65 92.24 180 top
CH173  0.1U_0402_10V6K  [C_0402]  167.71 25.76 90 top
CH176  1U_0402_6.3V6K  [C_0402]  165.11 24.68 90 top
CH177  22U_0603_6.3V6M  [C_0603]  183.65 38.41 90 bottom
CH178  22U_0603_6.3V6M  [C_0603]  182.38 38.41 90 bottom
CH179  1U_0402_6.3V6K  [C_0402]  181.49 38.39 90 top
CH180  1U_0402_6.3V6K  [C_0402]  155.66 42.79 180 top
CH181  22U_0603_6.3V6M  [C_0603]  157.81 45.84 180 top
CH182  22U_0603_6.3V6M  [C_0603]  155.39 45.84 180 top
CH183  1U_0402_6.3V6K  [C_0402]  165.98 36.23 180 top
CH184  10U_0402_6.3V6M  [C_0402]  167.27 37.12 90 top
CH185  10U_0402_6.3V6M  [C_0402]  166.38 37.12 90 top
CH186  0.1U_0402_10V6K  [C_0402]  170.85 24.32 90 top
CH187  1U_0402_6.3V6K  [C_0402]  178.71 21.57 0 top
CH188  1U_0402_6.3V6K  [C_0402]  173.42 32.46 0 top
CH189  0.1U_0402_10V7K  [C_0402]  175.73 26.53 180 top
CH190  0.1U_0402_10V7K  [C_0402]  159 32.36 180 top
CH191  0.1U_0402_10V7K  [C_0402]  158.84 28.82 180 top
CH192  0.1U_0402_10V7K  [C_0402]  155.9 22.99 270 top
CH197  0.1U_0402_10V7K  [C_0402]  81.4 83.1 180 bottom
CH200  0.1U_0402_10V6K  [C_0402]  171.97 25.24 90 top
CH201  22U_0603_6.3V6M  [C_0603]  177.81 28.69 90 top
CH202  22U_0603_6.3V6M  [C_0603]  176.6 29.07 180 top
CH203  0.1U_0402_10V6K  [C_0402]  170.95 28.13 270 top
CH204  1U_0402_6.3V6K  [C_0402]  123.19 94.65 180 top
CI9  0.1U_0402_10V6K  [C_0402]  286.45 51.55 0 bottom
CI10  0.1U_0402_10V6K  [C_0402]  286.45 50.66 0 bottom
CI11  47U_0805_6.3V6M  [C_0805]  293.72 45.84 180 bottom
CI12  10U_0603_6.3V6M  [C_0603]  293.57 47.36 180 bottom
CI13  0.1U_0402_10V6K  [C_0402]  293.46 48.5 180 bottom
CI16  0.1U_0402_10V6K  [C_0402]  285.43 32.38 0 bottom
CI17  47U_0805_6.3V6M  [C_0805]  292.83 28.44 180 top
CI18  10U_0603_6.3V6M  [C_0603]  292.81 26.91 180 top
CI19  0.1U_0402_10V6K  [C_0402]  292.82 25.77 180 top
CI20  0.1U_0402_10V6K  [C_0402]  285.43 31.49 0 bottom
CI23  0.1U_0402_10V6K  [C_0402]  282.84 38.27 90 top
CI24  1U_0402_6.3V6K  [C_0402]  290.41 40.38 180 bottom
CL15  0.1U_0402_10V6K  [C_0402]  289.62 46.09 0 bottom
CL19  0.1U_0402_10V6K  [C_0402]  282.48 48.89 0 bottom
CL20  0.1U_0402_10V6K  [C_0402]  285.58 46.79 180 top
CL21  0.1U_0402_10V6K  [C_0402]  283.98 42.71 90 top
CL22  0.1U_0402_10V6K  [C_0402]  287.42 46.79 180 top
CL24  0.1U_0402_10V6K  [C_0402]  282.46 40.71 270 bottom
CL30  0.1U_0402_10V6K  [C_0402]  288.55 39.79 90 bottom
CL31  0.1U_0402_10V6K  [C_0402]  287.66 39.79 90 bottom
CL32  0.1U_0402_10V6K  [C_0402]  283.98 45.53 270 top
CL33  10P_1206_2KV8J  [C_1206]  289.97 97.33 125.8 bottom
CL34  0.1U_0402_10V6K  [C_0402]  285.25 40.66 270 bottom
CL35  1U_0402_6.3V6K  [C_0402]  284.36 40.66 270 bottom
CL36  10P_0402_25V8J  [C_0402]  281.82 45 90 bottom
CL37  10P_0402_25V8J  [C_0402]  281.82 44.14 270 bottom
CL39  1U_0402_6.3V6K  [C_0402]  280.68 52.29 90 bottom
CL41  0.01U_0402_16V7K  [C_0402]  294.52 84.01 270 top
CL42  0.1U_0402_10V7K  [C_0402]  283.35 40.71 270 bottom
CL43  4.7U_0402_6.3V6M  [C_0402]  289.62 46.98 0 bottom
CL44  4.7U_0402_6.3V6M  [C_0402]  283.35 47.28 90 top
CL47  0.1U_0402_10V6K  [C_0402]  290.54 44.69 180 bottom
CL48  0.1U_0402_10V6K  [C_0402]  290.54 43.81 180 bottom
CLRP1  SHORT PADS  [SHORTPADS]  176.29 14.21 180 bottom
CM3  0.01U_0402_16V7K  [C_0402]  264.35 37.28 0 bottom
CM4  0.1U_0402_10V6K  [C_0402]  264.35 34.58 0 bottom
CM10  0.1U_0402_10V6K  [C_0402]  271.08 36.12 180 bottom
CM11  0.1U_0402_10V6K  [C_0402]  271.08 37.19 180 bottom
CM12  0.01U_0402_16V7K  [C_0402]  271.08 34.92 180 bottom
CM24  1U_0402_6.3V6K  [C_0402]  263.79 41.14 90 top
CM141  0.1U_0402_10V6K  [C_0402]  264.35 35.93 0 bottom
CM228  4.7U_0603_6.3V6K  [C_0603]  265.06 39.04 90 bottom
CM229  0.01U_0402_16V7K  [C_0402]  269.12 41.27 90 top
CM823  0.01U_0402_16V7K  [C_0402]  272.68 31.36 0 top
CM837  0.1U_0402_10V6K  [C_0402]  272.68 32.25 0 top
CM838  0.1U_0402_10V6K  [C_0402]  267.73 29.96 270 top
CM839  0.1U_0402_10V6K  [C_0402]  268.61 29.96 270 top
CM840  0.1U_0402_10V6K  [C_0402]  272.55 40 0 top
CM841  0.01U_0402_16V7K  [C_0402]  272.55 39.11 0 top
CM842  0.1U_0402_10V6K  [C_0402]  263.92 29.96 270 top
CM843  0.1U_0402_10V6K  [C_0402]  272.81 34.1 270 top
CN1  22U_0603_6.3V6M  [C_0603]  186.46 28.84 90 top
CN2  .1U_0402_16V7K  [C_0402]  184.52 28.9 90 top
CN6  22U_0603_6.3V6M  [C_0603]  199.78 29.01 90 top
CN7  .1U_0402_16V7K  [C_0402]  201.43 29 90 top
CN8  .1U_0402_16V7K  [C_0402]  185.4 28.9 90 top
CN9  1000P_0402_50V7K  [C_0402]  202.32 29 90 top
CN20  0.1U_0402_10V7K  [C_0402]  192.29 35.88 270 bottom
CN21  0.1U_0402_10V7K  [C_0402]  191.4 35.88 270 bottom
CS12  1000P_0402_50V7K  [C_0402]  194.95 18.58 90 bottom
CS13  0.1U_0402_10V6K  [C_0402]  195.84 18.58 90 bottom
CS14  1U_0402_6.3V6K  [C_0402]  196.73 18.58 90 bottom
CS15  10U_0603_6.3V6M  [C_0603]  197.86 18.32 90 bottom
CS25  0.01U_0402_16V7K  [C_0402]  192.16 17.47 270 top
CS26  0.01U_0402_16V7K  [C_0402]  193.05 17.47 270 top
CS27  0.01U_0402_16V7K  [C_0402]  191.14 17.47 270 top
CS28  0.01U_0402_16V7K  [C_0402]  190.26 17.47 270 top
CT79  22P_0402_50V8J  [C_0402]  149.87 18.8 0 bottom
CT80  0.01U_0402_16V7K  [C_0402]  108.39 84.83 0 top
CT81  0.1U_0201_10V6K  [C_0201]  60.68 50.92 0 bottom
CT82  2200P_0402_25V7K  [C_0402]  63.76 49.98 270 bottom
CT83  2200P_0402_25V7K  [C_0402]  147.19 76.01 270 top
CT84  2200P_0402_25V7K  [C_0402]  212.38 14.39 90 bottom
CT85  2200P_0402_25V7K  [C_0402]  63.76 48.2 270 bottom
CV50  47U_0805_6.3V6M  [C_0805]  161.41 76.06 270 top
CV51  10U_0603_6.3V6M  [C_0603]  164.6 78.74 270 top
CV52  0.1U_0402_10V7K  [C_0402]  160.66 82.49 90 top
CV53  0.1U_0402_10V7K  [C_0402]  163 80.66 270 top
CV54  0.01U_0402_16V7K  [C_0402]  148.43 80.85 90 top
CV70  10P_0402_50V8J  [C_0402]  178.44 72.63 180 bottom
CV71  10P_0402_50V8J  [C_0402]  175.65 72.63 0 bottom
CV72  0.1U_0402_10V7K  [C_0402]  163.55 82.37 0 top
CV79  10U_0603_6.3V6M  [C_0603]  168.44 95.81 90 top
CV80  10U_0603_6.3V6M  [C_0603]  174.29 90.74 0 top
CV83  22U_0603_6.3V6M  [C_0603]  176.55 94.81 0 top
CV84  22U_0603_6.3V6M  [C_0603]  176.08 84.04 180 top
CV85  22U_0603_6.3V6M  [C_0603]  182.7 105.78 180 top
CV86  22U_0603_6.3V6M  [C_0603]  166.71 97.34 270 top
CV87  1U_0402_6.3V6K  [C_0402]  161.88 92.46 0 top
CV88  1U_0402_6.3V6K  [C_0402]  161.88 93.44 0 top
CV89  1U_0402_6.3V6K  [C_0402]  161.88 94.51 0 top
CV90  1U_0402_6.3V6K  [C_0402]  161.88 91.47 0 top
CV91  4.7U_0603_6.3V6K  [C_0603]  161.49 95.61 0 top
CV92  4.7U_0603_6.3V6K  [C_0603]  161.46 90.23 0 top
CV93  10U_0603_6.3V6M  [C_0603]  147.96 83.05 90 bottom
CV94  10U_0603_6.3V6M  [C_0603]  150.44 104.36 180 bottom
CV95  10U_0603_6.3V6M  [C_0603]  147.2 107.72 270 bottom
CV96  22U_0603_6.3V6M  [C_0603]  149.36 84.51 270 bottom
CV97  22U_0603_6.3V6M  [C_0603]  149.17 105.63 0 bottom
CV100  1U_0402_6.3V6K  [C_0402]  175.85 93.61 180 top
CV101  1U_0402_6.3V6K  [C_0402]  165.62 96.84 270 top
CV102  1U_0402_6.3V6K  [C_0402]  176.06 89.68 0 top
CV103  1U_0402_6.3V6K  [C_0402]  171.89 96.79 270 top
CV112  1U_0402_6.3V6K  [C_0402]  176.92 92.45 0 top
CV113  1U_0402_6.3V6K  [C_0402]  177 84.9 90 top
CV114  0.1U_0402_10V7K  [C_0402]  160.94 84.65 90 top
CV117  0.1U_0402_10V7K  [C_0402]  172.65 82.06 270 top
CV118  0.1U_0402_10V7K  [C_0402]  149.46 100.7 0 top
CV119  1U_0402_6.3V6K  [C_0402]  149.46 99.69 0 top
CV120  4.7U_0603_6.3V6K  [C_0603]  148.73 101.97 0 top
CV152  0.1U_0402_10V7K  [C_0402]  169.88 98.21 0 top
CV153  0.1U_0402_10V7K  [C_0402]  176.94 88.32 270 top
CV154  0.1U_0402_10V7K  [C_0402]  173.34 98.55 90 top
CV156  22U_0603_6.3V6M  [C_0603]  149.02 101.72 0 bottom
CV158  820P_0402_25V7  [C_0402]  189.18 124.98 90 bottom
CV160  10U_0603_6.3V6M  [C_0603]  173.5 119.99 270 top
CV161  10U_0603_6.3V6M  [C_0603]  188.1 130.59 90 top
CV162  10U_0603_6.3V6M  [C_0603]  188.86 122.35 90 bottom
CV163  10U_0603_6.3V6M  [C_0603]  172.99 123.39 270 bottom
CV164  10U_0603_6.3V6M  [C_0603]  173.5 130.59 90 top
CV165  1U_0402_6.3V6K  [C_0402]  187.84 127.88 270 top
CV166  1U_0402_6.3V6K  [C_0402]  173.6 129.35 270 top
CV167  1U_0402_6.3V6K  [C_0402]  187.97 122.62 270 top
CV168  10U_0603_6.3V6M  [C_0603]  169.3 127.31 270 bottom
CV169  10U_0603_6.3V6M  [C_0603]  168.8 130.59 90 top
CV170  10U_0603_6.3V6M  [C_0603]  168.79 119.69 270 top
CV171  10U_0603_6.3V6M  [C_0603]  154.2 119.59 270 top
CV172  10U_0603_6.3V6M  [C_0603]  169.18 123.19 90 bottom
CV173  1U_0402_6.3V6K  [C_0402]  154.4 121.4 270 top
CV174  1U_0402_6.3V6K  [C_0402]  162.16 128.15 270 top
CV175  1U_0402_6.3V6K  [C_0402]  168.67 123.51 270 top
CV177  820P_0402_25V7  [C_0402]  203.8 73.67 0 bottom
CV179  10U_0603_6.3V6M  [C_0603]  209.16 74.98 0 top
CV180  10U_0603_6.3V6M  [C_0603]  198.56 74.98 180 top
CV181  10U_0603_6.3V6M  [C_0603]  201.62 90.03 0 bottom
CV182  10U_0603_6.3V6M  [C_0603]  209.16 89.58 0 top
CV183  10U_0603_6.3V6M  [C_0603]  198.46 89.58 180 top
CV184  1U_0402_6.3V6K  [C_0402]  206.72 83.18 180 top
CV185  1U_0402_6.3V6K  [C_0402]  206.72 81.38 180 top
CV186  1U_0402_6.3V6K  [C_0402]  196.43 87.2 90 top
CV187  10U_0603_6.3V6M  [C_0603]  209.9 95.24 0 top
CV188  10U_0603_6.3V6M  [C_0603]  201.66 94.86 0 bottom
CV189  10U_0603_6.3V6M  [C_0603]  202.7 110.48 90 bottom
CV190  10U_0603_6.3V6M  [C_0603]  198.32 95.37 180 top
CV191  10U_0603_6.3V6M  [C_0603]  202 109.97 0 top
CV192  1U_0402_6.3V6K  [C_0402]  209 103.56 0 top
CV193  1U_0402_6.3V6K  [C_0402]  203.86 107.41 90 top
CV194  1U_0402_6.3V6K  [C_0402]  207.92 95.06 180 bottom
CV199  820P_0402_25V7  [C_0402]  204.68 110.48 180 bottom
CV200  820P_0402_25V7  [C_0402]  153.81 125.52 90 bottom
CV202  0.1U_0402_10V7K  [C_0402]  175.12 82.36 180 top
CV206  1U_0402_6.3V6K  [C_0402]  175.12 89.17 180 top
CV207  1U_0402_6.3V6K  [C_0402]  171 96.79 270 top
CV208  1U_0402_6.3V6K  [C_0402]  163.84 96.87 270 top
CV209  1U_0402_6.3V6K  [C_0402]  175.4 85.61 180 top
CV210  1U_0402_6.3V6K  [C_0402]  175.12 88.28 180 top
CV211  1U_0402_6.3V6K  [C_0402]  164.73 96.87 270 top
CV212  0.1U_0402_10V7K  [C_0402]  145.29 76.24 90 bottom
CV213  4.7U_0603_6.3V6K  [C_0603]  175.68 72.58 90 top
CV214  1U_0402_6.3V6K  [C_0402]  171.85 76.56 0 top
CV373  10U_0603_6.3V6M  [C_0603]  188.1 119.99 270 top
CV374  1U_0402_6.3V6K  [C_0402]  187.9 125.23 90 top
CV375  1U_0402_6.3V6K  [C_0402]  173.6 123.75 270 top
CV376  1U_0402_6.3V6K  [C_0402]  173.62 121.07 90 top
CV377  1U_0402_6.3V6K  [C_0402]  179.9 130.43 90 top
CV378  1U_0402_6.3V6K  [C_0402]  184.9 117.54 180 top
CV379  1U_0402_6.3V6K  [C_0402]  175.76 117.59 180 top
CV380  1U_0402_6.3V6K  [C_0402]  187.84 129.61 270 top
CV381  10U_0603_6.3V6M  [C_0603]  154.2 130.59 90 top
CV382  1U_0402_6.3V6K  [C_0402]  154.44 123.13 270 top
CV383  1U_0402_6.3V6K  [C_0402]  160.6 128.15 270 top
CV384  1U_0402_6.3V6K  [C_0402]  154.4 129.35 270 top
CV385  1U_0402_6.3V6K  [C_0402]  168.67 120.82 90 top
CV386  1U_0402_6.3V6K  [C_0402]  154.31 127.57 270 top
CV387  1U_0402_6.3V6K  [C_0402]  156.75 125.29 180 top
CV388  1U_0402_6.3V6K  [C_0402]  168.98 121.23 90 bottom
CV389  10U_0603_6.3V6M  [C_0603]  201.86 74.57 180 bottom
CV390  1U_0402_6.3V6K  [C_0402]  208.43 74.67 180 bottom
CV391  1U_0402_6.3V6K  [C_0402]  199.8 75.18 0 top
CV392  1U_0402_6.3V6K  [C_0402]  208.11 75.17 180 top
CV393  1U_0402_6.3V6K  [C_0402]  195.08 86.91 90 bottom
CV394  1U_0402_6.3V6K  [C_0402]  207.92 89.48 180 top
CV395  1U_0402_6.3V6K  [C_0402]  203.86 77.54 270 top
CV396  1U_0402_6.3V6K  [C_0402]  207.92 89.89 180 bottom
CV397  10U_0603_6.3V6M  [C_0603]  209.16 109.96 0 top
CV398  1U_0402_6.3V6K  [C_0402]  199.8 95.06 0 bottom
CV399  1U_0402_6.3V6K  [C_0402]  206.72 103.56 180 top
CV400  1U_0402_6.3V6K  [C_0402]  209 101.76 0 top
CV401  1U_0402_6.3V6K  [C_0402]  206.72 101.76 180 top
CV402  1U_0402_6.3V6K  [C_0402]  199.45 95.49 0 top
CV403  1U_0402_6.3V6K  [C_0402]  207.92 109.76 180 top
CV404  1U_0402_6.3V6K  [C_0402]  196.36 106.72 270 top
CV499  0.1U_0402_10V7K  [C_0402]  153.18 77.19 0 top
CV531  0.22U_0201_6.3V6M  [C_0201]  151.47 83.46 180 top
CV532  0.22U_0201_6.3V6M  [C_0201]  151.47 82.82 180 top
CV533  0.22U_0201_6.3V6M  [C_0201]  153.12 84.47 180 top
CV534  0.22U_0201_6.3V6M  [C_0201]  153.12 83.84 180 top
CV535  0.22U_0201_6.3V6M  [C_0201]  151.47 84.86 180 top
CV536  0.22U_0201_6.3V6M  [C_0201]  151.47 85.49 180 top
CV537  0.22U_0201_6.3V6M  [C_0201]  153.12 86.51 180 top
CV538  0.22U_0201_6.3V6M  [C_0201]  153.12 85.87 180 top
CV539  0.22U_0201_6.3V6M  [C_0201]  151.47 86.89 180 top
CV540  0.22U_0201_6.3V6M  [C_0201]  151.47 87.52 180 top
CV541  0.22U_0201_6.3V6M  [C_0201]  153.12 88.54 180 top
CV542  0.22U_0201_6.3V6M  [C_0201]  153.12 87.9 180 top
CV543  0.22U_0201_6.3V6M  [C_0201]  151.47 88.92 180 top
CV544  0.22U_0201_6.3V6M  [C_0201]  151.47 89.55 180 top
CV545  0.22U_0201_6.3V6M  [C_0201]  153.12 90.57 180 top
CV546  0.22U_0201_6.3V6M  [C_0201]  153.12 89.94 180 top
CV547  0.22U_0201_6.3V6M  [C_0201]  151.47 91.59 180 top
CV548  0.22U_0201_6.3V6M  [C_0201]  151.47 90.95 180 top
CV550  0.22U_0201_6.3V6M  [C_0201]  153.12 91.97 180 top
CV551  0.22U_0201_6.3V6M  [C_0201]  153.12 92.6 180 top
CV552  0.22U_0201_6.3V6M  [C_0201]  151.47 93.62 180 top
CV557  0.22U_0201_6.3V6M  [C_0201]  151.47 92.98 180 top
CV558  0.22U_0201_6.3V6M  [C_0201]  153.12 94 180 top
CV559  0.22U_0201_6.3V6M  [C_0201]  153.12 94.63 180 top
CV560  0.22U_0201_6.3V6M  [C_0201]  151.47 95.65 180 top
CV561  0.22U_0201_6.3V6M  [C_0201]  151.47 95.02 180 top
CV562  0.22U_0201_6.3V6M  [C_0201]  153.12 96.03 180 top
CV563  0.22U_0201_6.3V6M  [C_0201]  153.12 96.67 180 top
CV564  0.22U_0201_6.3V6M  [C_0201]  151.47 97.05 180 top
CV565  0.22U_0201_6.3V6M  [C_0201]  151.47 97.68 180 top
CV566  0.22U_0201_6.3V6M  [C_0201]  153.12 98.06 180 top
CV567  0.22U_0201_6.3V6M  [C_0201]  153.12 98.7 180 top
CV573  0.1U_0402_10V7K  [C_0402]  147.96 109.21 270 top
CV576  8.2P_0402_50V8D  [C_0402]  62.8 34.15 0 top
CV577  10U_0603_6.3V6M  [C_0603]  62.68 35.3 0 top
CV578  1U_0603_25V6  [C_0603]  67.13 20.69 180 top
CV579  0.1U_0402_25V6  [C_0402]  62.8 25.01 0 top
CV580  0.1U_0402_10V6K  [C_0402]  52.89 36.36 0 bottom
CV581  0.1U_0402_10V6K  [C_0402]  52.89 37.25 0 bottom
CV582  0.1U_0402_10V6K  [C_0402]  229.83 46.73 180 bottom
CV583  8.2P_0402_50V8D  [C_0402]  229.83 45.71 180 bottom
CV584  10U_0603_6.3V6M  [C_0603]  230.83 46.85 0 bottom
CV585  0.1U_0402_10V6K  [C_0402]  52.89 38.14 0 bottom
CV586  0.1U_0402_10V6K  [C_0402]  52.89 39.03 0 bottom
CV587  0.1U_0402_10V6K  [C_0402]  52.89 39.92 0 bottom
CV588  0.1U_0402_10V6K  [C_0402]  52.89 40.8 0 bottom
CV589  0.1U_0402_10V6K  [C_0402]  52.89 41.82 0 bottom
CV590  0.1U_0402_10V6K  [C_0402]  52.89 42.71 0 bottom
CV591  0.1U_0402_10V6K  [C_0402]  52.89 35.47 0 bottom
CV592  0.1U_0402_10V6K  [C_0402]  52.89 34.58 0 bottom
CV597  10U_0603_6.3V6M  [C_0603]  296.24 66.79 180 bottom
CV598  0.1U_0402_10V6K  [C_0402]  296.25 67.94 180 bottom
CV599  0.1U_0402_25V6  [C_0402]  295.46 61.81 0 bottom
CV600  0.1U_0402_25V6  [C_0402]  295.46 71.62 0 bottom
CV601  0.1U_0402_25V6  [C_0402]  295.46 78.35 0 bottom
CV825  0.1U_0402_10V6K  [C_0402]  260.91 32.6 0 top
CV826  0.1U_0402_10V6K  [C_0402]  260.91 33.49 0 top
CV827  0.1U_0402_10V6K  [C_0402]  260.94 39.84 0 top
CV828  0.1U_0402_10V6K  [C_0402]  260.94 38.95 0 top
CV829  0.1U_0402_10V6K  [C_0402]  260.94 37.04 0 top
CV830  0.1U_0402_10V6K  [C_0402]  260.94 36.15 0 top
CV831  0.1U_0402_10V6K  [C_0402]  260.94 34.38 0 top
CV832  0.1U_0402_10V6K  [C_0402]  260.94 35.26 0 top
CV833  0.1U_0402_10V7K  [C_0402]  175.3 96.52 270 top
CV834  22U_0603_6.3V6M  [C_0603]  180.28 105.76 180 top
CV835  1U_0402_6.3V6K  [C_0402]  161.83 85.74 0 top
CV836  1U_0402_6.3V6K  [C_0402]  161.92 88.26 0 top
CV837  1U_0402_6.3V6K  [C_0402]  161.92 89.16 0 top
CV838  1U_0402_6.3V6K  [C_0402]  159.31 97.11 90 top
CV839  4.7U_0603_6.3V6K  [C_0603]  161.29 87.2 0 top
CV840  4.7U_0603_6.3V6K  [C_0603]  158.28 98.29 270 top
CV841  10U_0603_6.3V6M  [C_0603]  169.96 95.81 90 top
CV842  10U_0603_6.3V6M  [C_0603]  173.03 95.38 90 top
CV843  0.1U_0402_10V7K  [C_0402]  174.89 81.4 0 top
CV844  10U_0603_6.3V6M  [C_0603]  174.39 86.68 0 top
CV845  10U_0603_6.3V6M  [C_0603]  174.64 92.51 0 top
CV846  0.1U_0402_10V7K  [C_0402]  160.75 79.54 180 top
CV847  0.1U_0402_10V7K  [C_0402]  160.96 97.5 0 top
CV848  1U_0402_6.3V6K  [C_0402]  162.32 78.87 0 top
CV849  4.7U_0603_6.3V6K  [C_0603]  146.57 84.51 270 bottom
CV850  0.1U_0402_10V7K  [C_0402]  161.4 96.64 0 top
CV851  1U_0402_6.3V6K  [C_0402]  166.39 117.64 0 top
CV852  1U_0402_6.3V6K  [C_0402]  160.6 130.43 90 top
CV853  1U_0402_6.3V6K  [C_0402]  162.4 130.43 90 top
CV854  1U_0402_6.3V6K  [C_0402]  153.81 128.21 270 bottom
CV855  1U_0402_6.3V6K  [C_0402]  153.81 129.99 270 bottom
CV856  1U_0402_6.3V6K  [C_0402]  169.17 129.48 270 bottom
CV857  1U_0402_6.3V6K  [C_0402]  168.67 127.93 90 top
CV858  1U_0402_6.3V6K  [C_0402]  157.32 117.6 0 top
CV859  22U_0603_6.3V6M  [C_0603]  188.6 131.24 90 bottom
CV860  22U_0603_6.3V6M  [C_0603]  188.73 119.43 270 bottom
CV861  22U_0603_6.3V6M  [C_0603]  172.99 120.14 270 bottom
CV862  22U_0603_6.3V6M  [C_0603]  172.99 127.64 270 bottom
CV863  22U_0603_6.3V6M  [C_0603]  172.86 130.86 90 bottom
CV864  22U_0603_6.3V6M  [C_0603]  153.68 131.24 90 bottom
CV865  22U_0603_6.3V6M  [C_0603]  153.94 123.21 270 bottom
CV866  22U_0603_6.3V6M  [C_0603]  153.94 118.69 90 bottom
CV867  22U_0603_6.3V6M  [C_0603]  169.18 120.14 270 bottom
CV868  22U_0603_6.3V6M  [C_0603]  169.3 130.86 90 bottom
CV869  1U_0402_6.3V6K  [C_0402]  185.54 125.29 0 top
CV870  1U_0402_6.3V6K  [C_0402]  188.48 127.83 270 bottom
CV871  1U_0402_6.3V6K  [C_0402]  188.48 129.73 270 bottom
CV872  1U_0402_6.3V6K  [C_0402]  188.73 120.44 90 bottom
CV873  1U_0402_6.3V6K  [C_0402]  172.86 129.73 270 bottom
CV874  1U_0402_6.3V6K  [C_0402]  181.7 128.15 270 top
CV875  1U_0402_6.3V6K  [C_0402]  179.9 128.15 270 top
CV876  1U_0402_6.3V6K  [C_0402]  181.7 130.43 90 top
CV877  1U_0402_6.3V6K  [C_0402]  201.18 95.49 0 top
CV878  1U_0402_6.3V6K  [C_0402]  206.38 95.49 0 top
CV879  1U_0402_6.3V6K  [C_0402]  208.11 95.49 0 top
CV880  1U_0402_6.3V6K  [C_0402]  206.46 110.35 180 bottom
CV881  1U_0402_6.3V6K  [C_0402]  208.24 110.35 180 bottom
CV882  1U_0402_6.3V6K  [C_0402]  198.18 109.85 0 top
CV883  1U_0402_6.3V6K  [C_0402]  199.96 109.85 0 top
CV884  1U_0402_6.3V6K  [C_0402]  206.08 109.85 180 top
CV885  22U_0603_6.3V6M  [C_0603]  199.21 90.03 0 bottom
CV886  22U_0603_6.3V6M  [C_0603]  198.71 74.47 180 bottom
CV887  22U_0603_6.3V6M  [C_0603]  209.52 74.47 0 bottom
CV888  22U_0603_6.3V6M  [C_0603]  205.94 90.03 180 bottom
CV889  22U_0603_6.3V6M  [C_0603]  209.01 90.09 0 bottom
CV890  22U_0603_6.3V6M  [C_0603]  200.67 110.48 90 bottom
CV891  22U_0603_6.3V6M  [C_0603]  198.71 94.86 180 bottom
CV892  22U_0603_6.3V6M  [C_0603]  206.11 94.86 180 bottom
CV893  22U_0603_6.3V6M  [C_0603]  209.01 94.86 0 bottom
CV894  22U_0603_6.3V6M  [C_0603]  209.12 110.73 0 bottom
CV895  1U_0402_6.3V6K  [C_0402]  206.57 74.67 180 bottom
CV896  1U_0402_6.3V6K  [C_0402]  209 81.38 0 top
CV897  1U_0402_6.3V6K  [C_0402]  203.64 75.17 0 top
CV898  1U_0402_6.3V6K  [C_0402]  206.32 75.18 180 top
CV899  1U_0402_6.3V6K  [C_0402]  209 83.18 0 top
CV900  1U_0402_6.3V6K  [C_0402]  199.45 89.53 0 top
CV901  1U_0402_6.3V6K  [C_0402]  202.19 89.48 180 top
CV902  1U_0402_6.3V6K  [C_0402]  196.36 78.22 90 top
CV903  0.01U_0402_16V7K  [C_0402]  185.3 114.8 0 bottom
CV904  0.01U_0402_16V7K  [C_0402]  156.73 116.2 180 bottom
CV905  0.01U_0402_16V7K  [C_0402]  192.16 76.7 90 bottom
CV906  0.01U_0402_16V7K  [C_0402]  193.68 105.27 0 bottom
CV909  0.1U_0402_10V7K  [C_0402]  159.36 83.07 180 top
CV910  0.1U_0402_10V7K  [C_0402]  159.36 82.2 180 top
CV911  1U_0402_6.3V6K  [C_0402]  144.33 65.65 180 top
CV912  4.7U_0603_6.3V6K  [C_0603]  144.35 64.51 180 top
CV913  0.1U_0402_10V7K  [C_0402]  162.76 84.36 180 top
CV914  0.1U_0402_10V7K  [C_0402]  162.7 83.05 180 top
CV915  1U_0402_6.3V6K  [C_0402]  144.33 59.65 180 top
CV916  4.7U_0603_6.3V6K  [C_0603]  144.35 60.7 180 top
CV917  0.1U_0402_25V6  [C_0402]  200.26 57.62 90 top
CV918  0.01UF_0402_25V7K  [C_0402]  201.25 54.28 180 top
CV919  0.01UF_0402_25V7K  [C_0402]  175.56 58.45 90 bottom
CV920  0.1U_0402_10V7K  [C_0402]  153.1 106.77 270 top
CV921  0.1U_0402_10V7K  [C_0402]  155.84 76.52 270 top
CV922  0.1U_0402_10V7K  [C_0402]  157.86 79.94 90 top
CV923  0.1U_0402_16V7K  [C_0402]  231.84 19.13 270 bottom
CZ4  0.01U_0402_16V7K  [C_0402]  211.49 12.61 180 top
CZ6  0.01U_0402_16V7K  [C_0402]  211.5 13.83 180 top
CZ8  10U_0603_6.3V6M  [C_0603]  208.35 12.5 90 top
CZ9  10U_0603_6.3V6M  [C_0603]  207.85 16.25 270 top
CZ11  1U_0603_10V6K  [C_0603]  217.5 11.93 0 top
CZ12  1U_0603_10V6K  [C_0603]  218.63 14.23 0 top
CZ28  0.1U_0402_10V6K  [C_0402]  131.25 94.97 180 top
CZ41  0.1U_0402_10V6K  [C_0402]  63.51 41.14 180 top
CZ43  0.1U_0402_10V6K  [C_0402]  208.42 50.71 90 bottom
CZ44  1U_0402_6.3V6K  [C_0402]  230.69 45.71 0 bottom
CZ47  0.1U_0402_10V6K  [C_0402]  133.89 96.26 0 top
CZ49  0.1U_0402_10V6K  [C_0402]  69.1 48.5 180 top
CZ57  2200P_0402_25V7K  [C_0402]  70.44 48.47 90 top
CZ86  0.1U_0402_10V7K  [C_0402]  131.44 100.65 270 bottom
CZ88  1U_0402_6.3V6K  [C_0402]  134.38 99.2 0 top
CZ95  2200P_0402_25V7K  [C_0402]  151.26 110.38 90 bottom
CZ96  1U_0402_6.3V6K  [C_0402]  134.38 100.32 0 top
CZ97  0.1U_0402_25V6  [C_0402]  130.72 100.28 180 top
CZ98  0.1U_0402_10V6K  [C_0402]  149.31 108.3 180 bottom
CZ102  0.1U_0402_10V6K  [C_0402]  150.35 16.8 0 top
CZ104  1U_0402_6.3V6K  [C_0402]  11.62 21.83 0 top
CZ105  0.1U_0402_10V6K  [C_0402]  14.01 35.47 0 top
CZ106  0.1U_0402_10V6K  [C_0402]  13.98 36.64 0 top
CZ107  47U_0805_6.3V6M  [C_0805]  10.84 21.2 0 bottom
CZ108  0.1U_0402_10V6K  [C_0402]  62.18 61.55 0 top
D1  -  [BAT54C-7-F_SOT23-3]  275.24 20.44 270 bottom
D2  -  [BAT54A-7-F_SOT23-3]  272.65 28.44 90 bottom
DA1  -  [TVNST52302AB0_SOT523-3]  271.85 23.04 180 top
DA2  AZ5125-02S.R7G_SOT23-3  [AZ5125-02SPR7G_SOT23-3]  276.62 11.85 0 top
DA3  AZ5125-02S.R7G_SOT23-3  [AZ5125-02SPR7G_SOT23-3]  271.92 11.85 0 top
DA4  AZ5125-02S.R7G_SOT23-3  [AZ5125-02SPR7G_SOT23-3]  293.38 21.99 0 bottom
DA5  AZ5125-02S.R7G_SOT23-3  [AZ5125-02SPR7G_SOT23-3]  294.01 12.16 180 bottom
DA6  -  [AZ5123-01F-R7GR_DFN1006P2X2]  297.08 8.01 45 bottom
DC2  BAT54CW-7-F_SOT323-3~D  [BAT54CW-7-F_SOT323-3]  152.78 20.46 180 bottom
DE4  -  [IP4223CZ6_SO6-6]  147.23 10.49 180 bottom
DE7  -  [RB751S40T1G_SOD523-2]  53.98 32.06 270 top
